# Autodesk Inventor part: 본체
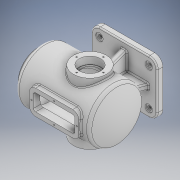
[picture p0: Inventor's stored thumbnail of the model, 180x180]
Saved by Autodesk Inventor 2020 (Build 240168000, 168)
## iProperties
Created: 2021-11
Part Number: 본체
Material: 일반
Document SubType Name: Modeling
Designer: Administrator
Density: 1 g/cm^3
Appearance: 기본값
Author: Administrator
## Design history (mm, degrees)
sketch "스케치1"
  geometry: L1 (-80, 65)-(80, 65); L2 (80, 65)-(80, -65); L3 (80, -65)-(-80, -65); L4 (-80, -65)-(-80, 65); L5 (-80, 65)-(80, -65); L6 (80, 65)-(-80, -65); 1 further point
  constraints: 12 end point, 2 midpoint, 2 parallel, 1 horizontal, 1 perpendicular
  dimensions: "d0" = 160 distance of L2.end L3.end; "d1" = 130 distance of L1.end L2.end
extrude "돌출1" new body sketch "스케치1" distance "d2" = 14; taper "d3" = 0 deg
sketch "스케치2"
  geometry: L1 (100, 179)-(-78.741, 179); L2 (-100, 114)-(110, 114); L3 (100, 179)-(100, 161.5); L4 (110, 146.5)-(85, 146.5); L5 (85, 146.5)-(85, 169); L6 (85, 169)-(-73.516, 169); L7 (0, 0)-(0, 222.03); L8 (100, 161.5)-(110, 161.5); L9 (110, 161.5)-(110, 114); L10 (80, 0)-(-80, 0) reference; L11 (80, 0)-(80, 14) reference; A1 r 110 centre (10, 114) between (-78.741, 179) and (-100, 114); A2 r 100 centre (10, 114) between (-73.516, 169) and (-90, 114); 1 further point
  constraints: 18 end point, 5 point on line, 4 point on circle, 3 horizontal, 2 centre point, 2 parallel, 2 perpendicular, 2 vertical
  dimensions: "d16" = 110 radius of A1; "d17" = 10 radial gap between concentric circles of A1 A2; "d24" = 210 distance from line of L2.start L9; "d25" = 114 distance between parallel lines of L10 L2; "d26" = 130 diameter of L1 L2; "d27" = 95 diameter of L8 L2; "d28" = 65 diameter of L4 L2; "d29" = 110 diameter of L6 L2; "d30" = 10 distance of L3.end L8.end; "d31" = 30 distance between parallel lines of L11 L9; "d32" = 25 distance of L4.start L4.end
revolve "회전1" stored, may be unused: angle "d18" = 90 deg
sketch "스케치5"
  geometry: L1 (-7, 7)-(7, 7); L2 (7, 7)-(7, -7); L3 (7, -7)-(-7, -7); L4 (-7, -7)-(-7, 7); L5 (-7, 7)-(7, -7); L6 (7, 7)-(-7, -7); 1 further point
  constraints: 12 end point, 2 midpoint, 2 parallel, 1 horizontal, 1 perpendicular
  dimensions: "d33" = 14 distance of L2.end L3.end; "d34" = 14 distance of L1.end L2.end
extrude "돌출2" join sketch "스케치5" stored distance "d35" = 14; taper "d36" = 0 deg
node "작업 평면2"
sketch "스케치7"
  geometry: L1 (-60, 30)-(60, 30); L2 (60, 30)-(60, -30); L3 (60, -30)-(-60, -30); L4 (-60, -30)-(-60, 30); L5 (-110, 47.5)-(-110, -47.5) reference; 2 further points
  constraints: 8 end point, 2 parallel, 1 horizontal, 1 horizontal alignment, 1 midpoint, 1 perpendicular
  dimensions: "d40" = 50 distance between parallel lines of L4 L5; "d41" = 120 distance of L1.start L1.end; "d42" = 60 distance of L1.end L2.end
extrude "돌출3" join sketch "스케치7" stored distance "d43" = 14; taper "d44" = 0 deg
sketch "스케치8"
  geometry: L1 (60, 30)-(-60, 30) reference; L2 (-60, 30)-(-60, -30) reference; L3 (-60, -30)-(60, -30) reference; L4 (60, -30)-(60, 30) reference; L5 (-50, 20)-(50, 20); L6 (50, 20)-(50, -20); L7 (50, -20)-(-50, -20); L8 (-50, -20)-(-50, 20); 1 further point
  constraints: 8 end point, 3 other
  dimensions: "d45" = 10 distance between parallel lines of L1 L5
extrude "돌출4" cut sketch "스케치8" stored distance "d46" = 14; taper "d47" = 0 deg
sketch "스케치9"
  geometry: L1 (10, 114)-(186.233, 114); L2 (186.233, 114)-(-208.049, 114); L3 (-17, 234.122)-(-17, -84.071); L4 (110, 66.5)-(110, 161.5) reference; C1 r 40 at (-17, 114); A1 r 110 centre (10, 114) between (-78.741, 179) and (-78.741, 49) reference; 2 further points
  constraints: 6 end point, 3 point on line, 1 centre point, 1 coincident, 1 horizontal, 1 vertical
  dimensions: "d48" = 127 distance between parallel lines of L3 L4; "d49" = 80 diameter of C1
extrude "돌출5" join sketch "스케치9" stored distance "d50" = 150; taper "d51" = 0 deg
sketch "스케치11"
  geometry: C1 r 40 at (0, 0) reference; C2 r 26 at (0, 0); 1 further point
  constraints: 1 centre point, 1 coincident
  dimensions: "d52" = 52 diameter of C2
extrude "돌출6" cut sketch "스케치11" distance "d53" = 18; taper "d54" = 0 deg
sketch "스케치12"
  geometry: C1 r 40 at (-17, 114) reference; C2 r 21 at (-17, 114); 1 further point
  constraints: 1 centre point, 1 coincident
  dimensions: "d55" = 42 diameter of C2
extrude "돌출7" cut sketch "스케치12" stored distance "d56" = 18; taper "d57" = 0 deg
fillet "모깎기1" dims "d58" = 0.3
sketch "스케치13"
  geometry: L1 (-39.739, 42.191)-(-50, 14); L2 (-65, 0)-(65, 0) reference; L3 (-65, 14)-(65, 14) reference; 2 further points
  constraints: 2 end point, 1 coincident, 1 point on line
  dimensions: "d59" = 110 deg angle of L2 L1; "d60" = 50 horizontal distance of L1.end point (0, 0); "d61" = 30 distance of L1.start L1.end
feature "리브1" sketch "스케치13" dims "d62" = 1, "d63" = 14, "d64" = 0, "d65" = 0, "d66" = 1, "d67" = 1
sketch "스케치14"
  geometry: L1 (49.739, 42.191)-(60, 14); L2 (80, 14)-(-80, 14) reference; 2 further points
  constraints: 2 end point, 1 coincident, 1 point on line
  dimensions: "d68" = 60 horizontal distance of L1.end point (0, 0); "d69" = 110 deg angle of L2 L1; "d71" = 30 distance of L1.start L1.end
feature "리브2" sketch "스케치14" dims "d72" = 1, "d73" = 14, "d74" = 0, "d75" = 0, "d76" = 1, "d77" = 1
fillet "모깎기2" dims "d78" = 10
fillet "모깎기3" dims "d79" = 10
fillet "모깎기4" dims "d80" = 20
fillet "모깎기5" dims "d81" = 15
fillet "모깎기6" dims "d82" = 5
fillet "모깎기7" dims "d83" = 3
fillet "모깎기8" dims "d84" = 3
fillet "모깎기9" dims "d85" = 3
fillet "모깎기10" dims "d86" = 3
node "작업 평면3"
sketch "스케치16"
  geometry: L1 (-20.739, 8.002)-(20.739, 8.002); L2 (20.739, 8.002)-(20.739, 1.998); L3 (20.739, 1.998)-(-20.739, 1.998); L4 (-20.739, 1.998)-(-20.739, 8.002); L5 (-20.739, 8.002)-(20.739, 1.998); L6 (20.739, 8.002)-(-20.739, 1.998); L7 (-60, 0)-(60, 0) reference; L8 (-80, 11)-(-80, 0) reference; 4 further points
  constraints: 4 end point, 3 midpoint, 1 vertical alignment, 2 other
  dimensions: "d88" = 5 distance from line of L7 point (0, 5); "d89" = 8.00204 distance between parallel lines of L7 L1; "d90" = 59.26052 distance between parallel lines of L8 L4
feature "엠보싱1" sketch "스케치16" dims "d16" = 110, "d17" = 10, "d24" = 210, "d25" = 114, "d26" = 130, "d27" = 95, "d28" = 65, "d29" = 110, "d30" = 10, "d31" = 30, "d32" = 25, "d91" = 0.5, "d92" = 0
sketch "스케치17" dims "d93" = 80
  geometry: L1 (0, 0)-(97.424, 0); C1 r 47.5 at (0, 0) reference; C2 r 32.5 at (0, 0) reference; 2 further points
  constraints: 2 end point, 1 coincident, 1 horizontal, 1 horizontal alignment, 1 point on line, 2 other
hole "구멍1" sketch "스케치17" at (40, 0) diameter "d94" = 3.242; stored, may be unused: countersink angle "d98" = 90 deg, drill point angle "d100" = 118 deg; dims "d95" = 11, "d96" = 4, "d97" = 2, "d99" = 13
sketch "스케치18" dims "d104" = 65
  geometry: L1 (0, 0)-(0, 85.407); C1 r 40 at (0, 0) reference; C2 r 26 at (0, 0) reference; 2 further points
  constraints: 2 end point, 1 coincident, 1 point on line, 1 vertical, 1 vertical alignment, 2 other
hole "구멍2" sketch "스케치18" at (0, 32.5) diameter "d105" = 3.242; stored, may be unused: countersink angle "d109" = 90 deg, drill point angle "d111" = 118 deg; dims "d106" = 11, "d107" = 4, "d108" = 2, "d110" = 13
revolve "회전2" stored, may be unused: angle "d115" = 90 deg
sketch "스케치19"
  geometry: L1 (0, -86.329)-(0, 146.225); L2 (-121.798, 0)-(129.16, 0); 5 further points
  constraints: 6 point on line, 4 end point, 1 horizontal, 1 vertical
  dimensions: "d116" = 55 distance of point (0, 0) point (-55, 0); "d117" = 55 distance from line of L1 point (55, 0); "d118" = 25 distance of point (0, 0) point (0, -25); "d119" = 25 distance of point (0, 0) point (0, 25)
hole "구멍3" sketch "스케치19" at (-55, 0), (0, -25), (55, 0), (0, 25) diameter "d120" = 3.242; stored, may be unused: countersink angle "d124" = 90 deg, drill point angle "d126" = 118 deg; dims "d121" = 9, "d122" = 4, "d123" = 2, "d125" = 11
sketch "스케치21"
  geometry: A1 r 20 centre (-60, -45) between (-80, -45) and (-60, -65) reference; A2 r 20 centre (60, -45) between (60, -65) and (80, -45) reference; A3 r 20 centre (-60, 45) between (-60, 65) and (-80, 45) reference; A4 r 20 centre (60, 45) between (80, 45) and (60, 65) reference; 5 further points
  constraints: 4 coincident
hole "구멍4" sketch "스케치21" at (-60, -45), (60, -45), (-60, 45), (60, 45) diameter "d127" = 9; stored, may be unused: countersink angle "d131" = 90 deg, drill point angle "d133" = 118 deg; dims "d128" = 11, "d129" = 18, "d130" = 2, "d132" = 16
node "솔리드1"
mirror "미러1"
mirror "미러2"
mirror "미러3"
pattern_circular "원형 패턴1" dims angle "d102" = 360 deg
pattern_circular "원형 패턴2" dims angle "d113" = 360 deg
mirror "미러4"
node "투영된 루프1"
node "투영된 루프3"
node "투영된 루프4"
node "투영된 루프5"
node "투영된 루프6"
feature "A9D066F2-1C7D-4E18-AEED-F7BC21143FA4" dims "d105" = 3.242, "d106" = 11, "d107" = 4, "d108" = 2, "d109" = 90 deg, "d110" = 13, "d111" = 118 deg
other parameters: "d39" = 184, "d87" = -116.5
